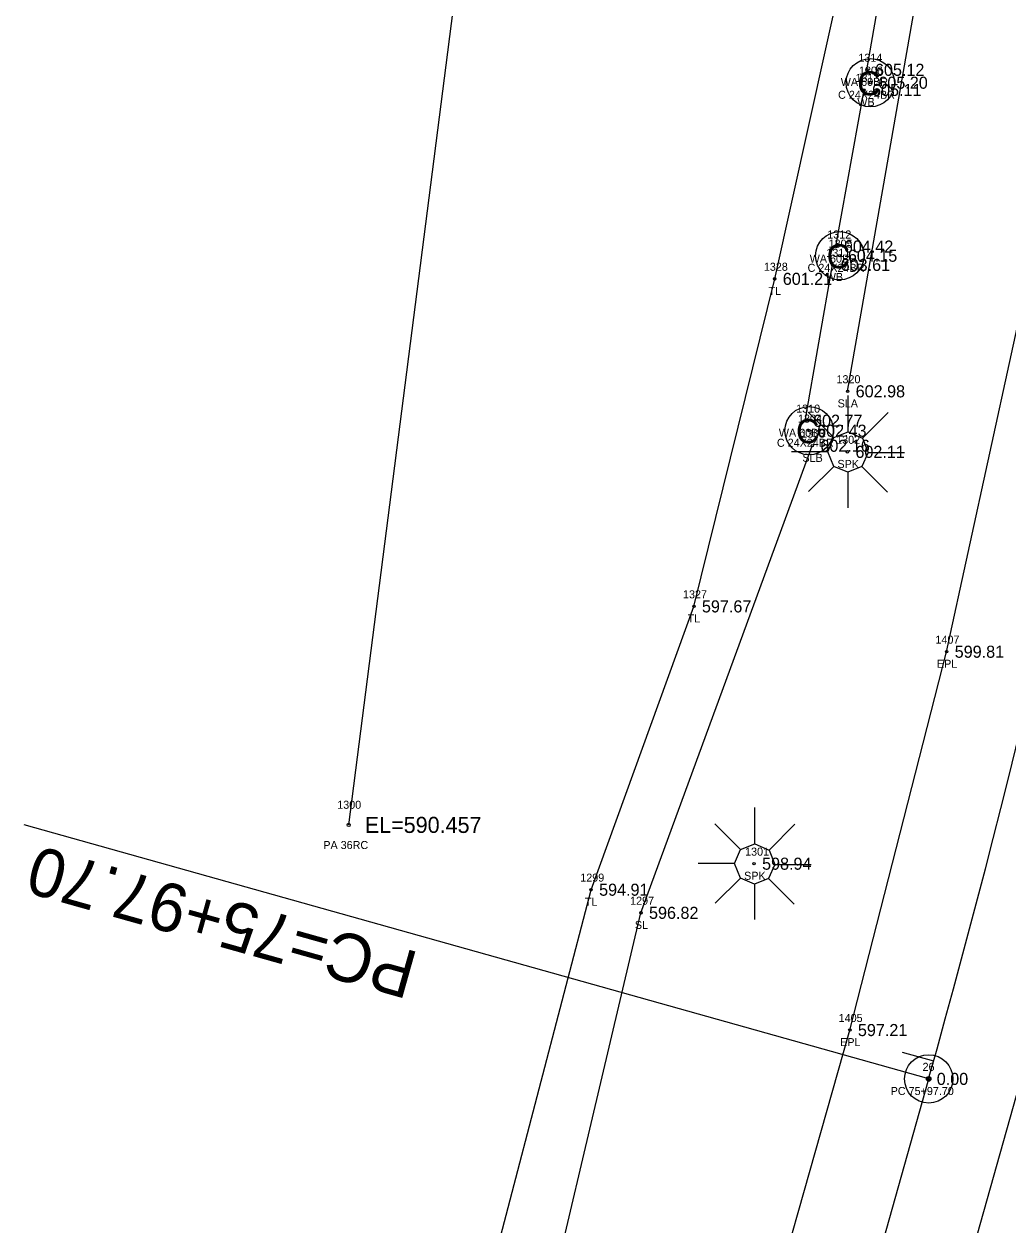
# Model space of a CAD drawing. Extents: x 1694813 to 1696862, y 1086485 to 1091027.
# Drawn here: x 1695673.6 to 1695795.7, y 1089706.2 to 1089855.4 of the extents above; entities that cross this region are included whole.
import ezdxf

# ---------------------------------------------------------------- set-up
doc = ezdxf.new("R2010")
doc.units = 0
for name, color, linetype in [('RD_EX_BldgApp', 7, 'Continuous'), ('RD_EX_BldgApp_txCode', 7, 'Continuous'), ('RD_EX_DR_Pipe', 7, 'Continuous'), ('RD_EX_DR_Pipe_txCode', 7, 'Continuous'), ('RD_EX_Misc_txCode', 7, 'Continuous'), ('RD_EX_Road', 7, 'Continuous'), ('RD_EX_Road_txCode', 7, 'Continuous'), ('RD_EX_TX_BldgApp_ELEV', 7, 'Continuous'), ('RD_EX_TX_Misc_ELEV', 7, 'Continuous'), ('RD_EX_TX_Road_ELEV', 7, 'Continuous'), ('RD_EX_TX_VEG_ELEV', 7, 'Continuous'), ('RD_EX_VEG', 7, 'Continuous'), ('RD_EX_VEG_txCode', 7, 'Continuous'), ('RD_HC_Cl', 7, 'Continuous'), ('RD_HC_Data', 7, 'Continuous'), ('RD_HC_Data_Tic', 7, 'Continuous'), ('RD_HC_Survey_ELEV', 7, 'Continuous'), ('RD_HC_txCode', 7, 'Continuous'), ('RD_SMD_Locator', 7, 'Continuous'), ('RD_TX_Pipe_ElevEX', 7, 'Continuous')]:
    doc.layers.add(name, color=color, linetype=linetype)

msp = doc.modelspace()

# ---------------------------------------------------------------- linework, layer by layer
at = {"layer": 'RD_EX_BldgApp'}
for p, q in [((1695778.23, 1089849.69), (1695781.58, 1089868.83)), ((1695774.37, 1089827.74), (1695777.87, 1089847.19)), ((1695770.54, 1089806.11), (1695773.97, 1089825.46)), ((1695775.91, 1089804.71), (1695775.91, 1089809.22)), ((1695774.13, 1089804.01), (1695770.94, 1089807.19)), ((1695777.66, 1089803.94), (1695780.86, 1089807.14)), ((1695773.38, 1089802.25), (1695768.86, 1089802.25)), ((1695778.39, 1089802.17), (1695782.89, 1089802.17)), ((1695774.1, 1089800.44), (1695770.98, 1089797.32)), ((1695775.87, 1089799.7), (1695775.87, 1089795.29)), ((1695777.61, 1089800.41), (1695780.8, 1089797.22)), ((1695764.32, 1089753.56), (1695764.32, 1089758.07)), ((1695762.53, 1089752.86), (1695759.35, 1089756.04)), ((1695766.07, 1089752.79), (1695769.27, 1089755.98)), ((1695761.79, 1089751.1), (1695757.27, 1089751.1)), ((1695766.79, 1089751.01), (1695771.29, 1089751.01)), ((1695762.51, 1089749.28), (1695759.39, 1089746.17)), ((1695766.02, 1089749.26), (1695769.21, 1089746.07)), ((1695764.28, 1089748.55), (1695764.28, 1089744.14))]:
    msp.add_line(p, q, dxfattribs=at)
for points in [[(1695774.13, 1089804.01), (1695775.91, 1089804.71), (1695777.66, 1089803.94), (1695778.39, 1089802.17), (1695777.61, 1089800.41), (1695775.87, 1089799.7), (1695774.1, 1089800.44), (1695773.38, 1089802.25)], [(1695762.53, 1089752.86), (1695764.32, 1089753.56), (1695766.07, 1089752.79), (1695766.79, 1089751.01), (1695766.02, 1089749.26), (1695764.28, 1089748.55), (1695762.51, 1089749.28), (1695761.79, 1089751.1)]]:
    msp.add_lwpolyline(points, close=True, dxfattribs=at)
for centre in [(1695778.65, 1089848.09), (1695774.86, 1089826.6), (1695771.05, 1089804.87)]:
    msp.add_circle(centre, 3, dxfattribs=at)
at = {"layer": 'RD_EX_DR_Pipe'}
msp.add_line((1695713.87, 1089755.91), (1695737.77, 1089941.97), dxfattribs=at)
at = {"layer": 'RD_EX_Road'}
for points in [[(1695813.78, 1089148.1), (1695805.56, 1089142.08), (1695776.44, 1089183.94), (1695749.27, 1089231.88), (1695730.49, 1089275.72), (1695714.87, 1089332.12), (1695707.87, 1089381.72), (1695706.58, 1089435.34), (1695711.58, 1089484.26), (1695722.15, 1089537.59), (1695749.04, 1089634.88), (1695776.11, 1089730.43), (1695788.13, 1089777.42), (1695798.89, 1089826.76), (1695807.1, 1089870.03), (1695814.71, 1089923.3), (1695820.51, 1089978.16), (1695824.04, 1090019.79), (1695832.76, 1090119.06), (1695841.25, 1090216.76), (1695850.36, 1090314.41), (1695859.24, 1090411.82), (1695868.09, 1090511.63), (1695876.75, 1090608.38)], [(1695735.35, 1089335.84), (1695728.69, 1089383.6), (1695727.9, 1089434.83), (1695732.68, 1089480.1), (1695743.4, 1089531.84), (1695770.35, 1089628.36), (1695797.63, 1089725.22), (1695809.49, 1089772.37), (1695818.34, 1089811.57), (1695820.65, 1089823.41), (1695822.99, 1089835.26), (1695829.18, 1089869.37), (1695836.32, 1089920.97), (1695842.44, 1089975.46), (1695846.49, 1090018.55), (1695849.32, 1090055.39), (1695850.91, 1090072.92), (1695855.09, 1090117.49), (1695863.53, 1090214.93), (1695872.56, 1090312.44), (1695881.69, 1090410.78), (1695890.45, 1090509.3), (1695899.01, 1090605.4)]]:
    msp.add_lwpolyline(points, dxfattribs=at)
at = {"layer": 'RD_EX_VEG'}
for points in [[(1695703.52, 1089329.03), (1695695, 1089381.13), (1695696.39, 1089435.79), (1695702.88, 1089488.39), (1695714.38, 1089541.02), (1695736.44, 1089639.8), (1695727.2, 1089683.67), (1695743.97, 1089747.86), (1695756.74, 1089783.05), (1695766.78, 1089823.73), (1695779.53, 1089881.29), (1695754.55, 1089939.82)], [(1695775.83, 1089809.76), (1695787.59, 1089876.92), (1695797.35, 1089923.06), (1695786.71, 1089936.12), (1695764.52, 1089939.24)], [(1695734.05, 1089676.69), (1695750.17, 1089744.99), (1695771.45, 1089803)]]:
    msp.add_lwpolyline(points, dxfattribs=at)
at = {"layer": 'RD_HC_Cl'}
msp.add_line((1695732.11, 1089532.85), (1695785.9, 1089724.36), dxfattribs=at)
msp.add_arc((1694493.64, 1090087.29), 1342.25, 344.31262, 354.86182, dxfattribs=at)
at = {"layer": 'RD_HC_Data'}
msp.add_line((1695785.9, 1089724.36), (1695673.55, 1089755.91), dxfattribs=at)
for radius in [3, 0.282]:
    msp.add_circle((1695785.9, 1089724.36), radius, dxfattribs=at)
at = {"layer": 'RD_HC_Data_Tic'}
msp.add_line((1695786.52, 1089726.58), (1695782.66, 1089727.65), dxfattribs=at)
at = {"layer": 'RD_SMD_Locator'}
for centre, radius in [((1695778.23, 1089849.69), 0.15), ((1695777.87, 1089847.19), 0.15), ((1695778.65, 1089848.09), 0.15), ((1695774.37, 1089827.74), 0.15), ((1695774.86, 1089826.6), 0.15), ((1695773.97, 1089825.46), 0.15), ((1695766.78, 1089823.73), 0.15), ((1695775.83, 1089809.76), 0.15), ((1695770.54, 1089806.11), 0.15), ((1695771.05, 1089804.87), 0.15), ((1695771.45, 1089803), 0.15), ((1695775.8, 1089802.24), 0.15), ((1695756.74, 1089783.05), 0.15), ((1695788.13, 1089777.42), 0.15), ((1695713.87, 1089755.91), 0.2), ((1695764.21, 1089751.09), 0.15), ((1695743.97, 1089747.86), 0.15), ((1695750.17, 1089744.99), 0.15), ((1695776.11, 1089730.43), 0.15), ((1695785.9, 1089724.36), 0.15)]:
    msp.add_circle(centre, radius, dxfattribs=at)

# ---------------------------------------------------------------- texts
at = {"layer": 'RD_EX_BldgApp'}
for p in [(1695777.02, 1089846.52), (1695773.23, 1089825.04), (1695769.42, 1089803.31)]:
    msp.add_text('C', height=3, dxfattribs=at).set_placement(p)
at = {"layer": 'RD_EX_BldgApp_txCode'}
for s, p in [('1306', (1695777.24, 1089849.09)), ('C 24X24BR', (1695774.65, 1089846.09)), ('1305', (1695773.47, 1089827.6)), ('C 24X24BR', (1695770.86, 1089824.6)), ('1304', (1695769.67, 1089805.87)), ('C 24X24BR', (1695767.05, 1089802.87)), ('1302', (1695774.41, 1089803.24)), ('SPK', (1695774.57, 1089800.24)), ('1301', (1695763.1, 1089752.09)), ('SPK', (1695762.98, 1089749.09))]:
    msp.add_text(s, height=1, dxfattribs=at).set_placement(p)
at = {"layer": 'RD_EX_DR_Pipe_txCode'}
for s, p in [('1300', (1695712.45, 1089757.91)), ('PA 36RC', (1695710.72, 1089752.91))]:
    msp.add_text(s, height=1, dxfattribs=at).set_placement(p)
at = {"layer": 'RD_EX_Misc_txCode'}
for s, p in [('1314', (1695777.17, 1089850.69)), ('WA 60BR', (1695774.98, 1089847.69)), ('1313', (1695776.81, 1089848.19)), ('WB', (1695777.03, 1089845.19)), ('1312', (1695773.31, 1089828.74)), ('WA 60BR', (1695771.12, 1089825.74)), ('1311', (1695773.19, 1089826.46)), ('WB', (1695773.12, 1089823.46)), ('1310', (1695769.44, 1089807.11)), ('WA 60BR', (1695767.29, 1089804.11))]:
    msp.add_text(s, height=1, dxfattribs=at).set_placement(p)
at = {"layer": 'RD_EX_Road_txCode'}
for s, p in [('1407', (1695786.74, 1089778.42)), ('EPL', (1695786.92, 1089775.42)), ('1405', (1695774.72, 1089731.43)), ('EPL', (1695774.9, 1089728.43))]:
    msp.add_text(s, height=1, dxfattribs=at).set_placement(p)
at = {"layer": 'RD_EX_TX_BldgApp_ELEV'}
for s, p in [('605.20', (1695779.65, 1089847.34)), ('604.15', (1695775.86, 1089825.85)), ('602.43', (1695772.05, 1089804.12)), ('602.11', (1695776.8, 1089801.49)), ('598.94', (1695765.21, 1089750.34))]:
    msp.add_text(s, height=1.5, dxfattribs=at).set_placement(p)
at = {"layer": 'RD_EX_TX_Misc_ELEV'}
for s, p in [('605.12', (1695779.23, 1089848.94)), ('605.11', (1695778.87, 1089846.44)), ('604.42', (1695775.37, 1089826.99)), ('603.61', (1695774.97, 1089824.71)), ('602.77', (1695771.54, 1089805.36))]:
    msp.add_text(s, height=1.5, dxfattribs=at).set_placement(p)
at = {"layer": 'RD_EX_TX_Road_ELEV'}
for s, p in [('599.81', (1695789.13, 1089776.67)), ('597.21', (1695777.11, 1089729.68))]:
    msp.add_text(s, height=1.5, dxfattribs=at).set_placement(p)
at = {"layer": 'RD_EX_TX_VEG_ELEV'}
for s, p in [('601.21', (1695767.78, 1089822.98)), ('602.98', (1695776.83, 1089809.01)), ('602.16', (1695772.45, 1089802.25)), ('597.67', (1695757.74, 1089782.3)), ('594.91', (1695744.97, 1089747.11)), ('596.82', (1695751.17, 1089744.24))]:
    msp.add_text(s, height=1.5, dxfattribs=at).set_placement(p)
at = {"layer": 'RD_EX_VEG_txCode'}
for s, p in [('1328', (1695765.43, 1089824.73)), ('TL', (1695766.01, 1089821.73)), ('1320', (1695774.45, 1089810.76)), ('SLA', (1695774.59, 1089807.76)), ('1303', (1695770.06, 1089804)), ('SLB', (1695770.22, 1089801)), ('1327', (1695755.39, 1089784.05)), ('TL', (1695755.97, 1089781.05)), ('1299', (1695742.63, 1089748.86)), ('TL', (1695743.2, 1089745.86)), ('1297', (1695748.82, 1089745.99)), ('SL', (1695749.41, 1089742.99))]:
    msp.add_text(s, height=1, dxfattribs=at).set_placement(p)
at = {"layer": 'RD_HC_Data'}
msp.add_text('PC=75+97.70', height=6, rotation=164.3126, dxfattribs=at).set_placement((1695722.78, 1089740.01))
at = {"layer": 'RD_HC_Survey_ELEV'}
msp.add_text('0.00', height=1.5, dxfattribs=at).set_placement((1695786.9, 1089723.61))
at = {"layer": 'RD_HC_txCode'}
for s, p in [('26', (1695785.14, 1089725.36)), ('PC 75+97.70', (1695781.18, 1089722.36))]:
    msp.add_text(s, height=1, dxfattribs=at).set_placement(p)
at = {"layer": 'RD_TX_Pipe_ElevEX'}
msp.add_text('EL=590.457', height=2, dxfattribs=at).set_placement((1695715.87, 1089754.91))

doc.saveas('drawing.dxf')
